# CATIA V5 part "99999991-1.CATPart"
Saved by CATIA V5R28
Part number: 99999991-1
Bounding box of the stored display mesh (mm): x -126.639 to 152.4, y -153.085 to 527.049, z -23.619 to 160.233
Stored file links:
  C:\Users\tjb1387\Desktop\99999991-1.CATPart
  C:\Program Files\Dassault Systemes\B28SP3PRALL\win_b64\startup\materials\Catalog.CATMaterial
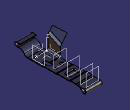
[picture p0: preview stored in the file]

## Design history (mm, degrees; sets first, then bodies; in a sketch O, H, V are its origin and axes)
SheetMetalParameters1: Thickness 4.826, BendRadius 14.224, KFactor 0.442616 {= log(min(100,max(20*SheetMetalParameters1.BendRadius,SheetMetalParameters1.Thickness)/SheetMetalParameters1.Thickness))/log(100)/2}, ReliefRadialLength 1, ReliefAxialLength 2, MinimumBendRadius 4, SHMJoggleCoeffRunout 3, JoggleCompensationOnWeb "C:\\Users\\gu900a\\Desktop\\"
AxisSystem1: origin (0, 0, 0), X (1, 0, 0), Y (0, 1, 0), Z (0, 0, 1)
Set1
  Plane1: type Offset, RefPlane ZX plane of AxisSystem1, Offset 127
  Set2
    Plane2: type Offset, RefPlane ZX plane of AxisSystem1, Offset 254 {= Plane1.Offset * 2}
    Plane3: type Offset, RefPlane ZX plane of AxisSystem1, Offset 381 {= Plane1.Offset * 3}
  Plane4: type Offset, RefPlane YZ plane of AxisSystem1, Offset 76.2
  Plane5: type Offset, RefPlane Plane3, Offset 50.8
Body1 (main body), material "Aluminium"
  a_Web1: Web_Thickness 4.826
  Sketch1 on face of a_Web1, origin (34.9218, 58.2231, 4.826), H (1, 0, 0), V (0, 1, 0)
    point P1 (0, 0)
  Hole1: placed by Sketch1, at (34.9218, 58.2231, 4.826) direction (0, 0, -1), diameter 6.35, through (limit type 6)
  Sketch2 on face of a_Web1, origin (0, 0, 9.652), H (1, 0, 0), V (0, 1, 0)
    line L1 (124.218, 79.1027) -> (89.298, 79.1027)
    line L2 (89.298, 79.1027) -> (89.298, 149.8672)
    line L3 (89.298, 149.8672) -> (124.218, 149.8672)
    line L4 (124.218, 149.8672) -> (124.218, 79.1027)
    horizontal: L1 H, L3 H
    vertical: L2 V, L4 V
  CutOut1: Direction Sketch2, EndLimit through (limit type 2), Orientation false, Profile Sketch2, StartLimit through (limit type 2), Thickness1 2, Thickness2 2
  Flange1: Guide edge [face of a_Web1 | face of a_Web1], Angle 43.7813 {= 2*atan(Flange1.Radius/Flange1.Length)}, KFacteur 0.442616 {= log(min(100,max(20*Flange1.Radius,SheetMetalParameters1.Thickness)/SheetMetalParameters1.Thickness))/log(100)/2}, Length 35.4, Radius 14.224 {= SheetMetalParameters1.BendRadius}
  Sketch3 on face of a_Web1, origin (0, 0, 14.478), H (1, 0, 0), V (0, 1, 0)
    line L1 (115.2392, 292.7397) -> (33.833, 292.7397)
    line L2 (33.833, 292.7397) -> (33.833, 339.4339)
    line L3 (33.833, 339.4339) -> (115.2392, 339.4339)
    line L4 (115.2392, 339.4339) -> (115.2392, 292.7397)
    horizontal: L1 H, L3 H
    vertical: L2 V, L4 V
  a_Stamp1: NewRoot_AttribNormalisation "No Standard", Stamp_FilletRadius 2, Stamp_IntersectFilletRadius 2
  Sketch4 on face of a_Web1, origin (41.698, 184.4635, 9.652), H (1, 0, 0), V (0, 1, 0)
    point P1 (0, 0)
  Hole2: placed by Sketch4, at (41.698, 184.4635, 9.652) direction (0, 0, -1), diameter 31.75, through (limit type 6)
  Sketch5 on face of a_Web1, origin (107.0492, 198.2207, 9.652), H (1, 0, 0), V (0, 1, 0)
    point P1 (0, 0)
  a_Stamp2: KFacteur 0.442616 {= SheetMetalParameters1.KFactor}, NewRoot_AttribNormalisation "No Standard", Stamp_FilletRadius 0.508, Stamp_IntersectFilletRadius 2
  Sketch6 on face of a_Web1, origin (152.4, 0, 0), H (0, 1, 0), V (0, 0, 1)
    line L1 (0, 0) -> (-29.0923, 0)
    arc A1 centre (-29.0923, 43.6421) radius 43.6421 from (-29.0923, 0) to (-64.8344, 18.5995) cw
    arc A2 centre (-112.9838, -15.1363) radius 58.7918 from (-64.8344, 18.5995) to (-114.2384, 43.6421) ccw
    line L2 (-114.2384, 43.6421) -> (-133.6324, 43.2281)
    horizontal: L1 H
    tangency: A1 L1, A2 A1, L2 A2
  Flange2: Guide edge [face of a_Web1 | face of a_Web1], KFacteur 0.442616 {= SheetMetalParameters1.KFactor}
  Flange3: Guide edge [face of Flange2 | face of Flange2], Angle 43.7813, KFacteur 0.442616 {= log(min(100,max(20*Flange3.Radius,SheetMetalParameters1.Thickness)/SheetMetalParameters1.Thickness))/log(100)/2}, Length 35.4, Radius 14.224 {= SheetMetalParameters1.BendRadius}
  Flange4: Guide edge [face of a_Web1 | face of a_Web1], Angle 90, KFacteur 0.442616 {= log(min(100,max(20*Flange4.Radius,SheetMetalParameters1.Thickness)/SheetMetalParameters1.Thickness))/log(100)/2}, Length 187.8, Radius 14.224 {= SheetMetalParameters1.BendRadius}
  Sketch7 on face of Flange4, origin (-19.05, 112.522, 19.05), H (0, 0, 1), V (0, -1, 0)
    line L1 (145.9428, 159.1396) -> (54.6468, -32.5692)
  FlatBend1: Angle 90, Axis Sketch7, FixedPoint vertex [face of Flange4 | face of Flange4 | face of Flange4 | face of Flange4], KFactor 0.442616 {= log(min(100,max(20*FlatBend1.FlatBendRadius,SheetMetalParameters1.Thickness)/SheetMetalParameters1.Thickness))/log(100)/2}, Radius 14.224 {= SheetMetalParameters1.BendRadius}
  Sketch8 on XY plane of AxisSystem1, origin (0, 0, 0), H (1, 0, 0), V (0, 1, 0)
    line L1 (0, 0) -> (152.4, 0)
    line L2 (152.4, 0) -> (152.4, 508)
    line L3 (152.4, 508) -> (0, 508)
    line L4 (0, 508) -> (0, 0)
    length L4 = 508
    distance L4 L2 = 152.4
    horizontal: L1 H, L3 H
    vertical: L2 V, L4 V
